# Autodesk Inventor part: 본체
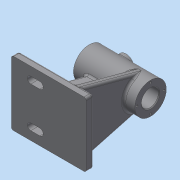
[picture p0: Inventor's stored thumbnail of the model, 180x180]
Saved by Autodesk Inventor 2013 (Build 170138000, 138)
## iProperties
Created: 2019-10
Part Number: 본체
Material: Generic
Document SubType Name: Modeling
Designer: Administrator
Density: 1 g/cm^3
Author: Administrator
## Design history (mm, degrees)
sketch "스케치1"
  geometry: L1 (0, 0)-(127.136, 0); L2 (0, 14.5)-(0, 21); L3 (0, 21)-(82, 21); L4 (82, 21)-(82, 11.5); L5 (82, 11.5)-(62, 11.5); L6 (62, 11.5)-(62, 14.5); L7 (62, 14.5)-(0, 14.5)
  constraints: 14 end point, 3 perpendicular, 2 parallel, 1 horizontal, 1 vertical alignment
  dimensions: "d0" = 42 diameter of L3 L1; "d2" = 29 diameter of L7 L1; "d3" = 23 diameter of L5 L1; "d4" = 62 distance of L6.end L2.start; "d5" = 82 distance between parallel lines of L4 L2
revolve "회전1" sketch "스케치1" stored, may be unused: angle "d6" = 90 deg
sketch "스케치2"
  geometry: C1 r 11.5 at (0, 0) reference; C2 r 2 at (0, 18)
  constraints: 1 centre point, 1 vertical alignment
  dimensions: "d7" = 18 distance of C1.centre C2.centre
hole "구멍1" sketch "스케치2" at (0, 18) diameter "d8" = 2.459; stored, may be unused: countersink angle "d12" = 82 deg, drill point angle "d14" = 118 deg; dims "d9" = 8, "d10" = 3.023, "d11" = 2, "d13" = 10
node "작업 평면1"
chamfer "모따기1" distance "d18" = 1; stored, may be unused: second distance "d19" = 2, angle "d20" = 45 deg
node "작업 평면2"
sketch "스케치3"
  geometry: C1 r 11 at (-25, 0); 1 further point
  constraints: 1 centre point, 1 horizontal alignment
  dimensions: "d22" = 25 distance of point (0, 0) C1.centre; "d23" = 22 diameter of C1
extrude "돌출1" join sketch "스케치3" stored distance "d24" = 10; taper "d25" = 0 deg
sketch "스케치4"
  geometry: C1 r 11 at (0, 0) reference; C2 r 7 at (0, 0); 1 further point
  constraints: 1 centre point, 1 coincident
  dimensions: "d26" = 14 diameter of C2
extrude "돌출2" cut sketch "스케치4" distance "d28" = 4; taper "d29" = 0 deg
sketch "스케치5"
  geometry: C1 r 7 at (0, 0) reference; C2 r 3.162 at (0, 0); 1 further point
  constraints: 1 centre point, 1 coincident
hole "구멍2" sketch "스케치5" at (0, 0) diameter "d30" = 4.917; stored, may be unused: countersink angle "d34" = 82 deg, drill point angle "d36" = 118 deg; dims "d31" = 8, "d32" = 3.023, "d33" = 2, "d35" = 10
fillet "모깎기1" dims "d37" = 3
node "작업 평면3"
sketch "스케치6"
  geometry: L1 (18, -43)-(-82, -43); L2 (-82, -43)-(-82, 43); L3 (-82, 43)-(18, 43); L4 (18, 43)-(18, -43); L5 (-82, 21)-(-82, -21) reference; 1 further point
  constraints: 8 end point, 2 parallel, 1 horizontal, 1 perpendicular
  dimensions: "d39" = 0 distance between parallel lines of L5 L2; "d40" = 100 distance of L1.start L1.end; "d41" = 86 distance of L1.end L2.end; "d42" = 43 distance from line of L1 point (0, 0)
extrude "돌출3" join sketch "스케치6" distance "d43" = 10; taper "d44" = 0 deg
fillet "모깎기2" dims "d45" = 3
sketch "스케치7"
  geometry: L1 (8, 31.5)-(20, 31.5); L2 (8, 22.5)-(20, 22.5); L3 (8, 34)-(20, 34); L4 (8, 20)-(20, 20); L5 (-18, 40)-(-18, -40) reference; A1 r 4.5 centre (8, 27) between (8, 31.5) and (8, 22.5); A2 r 4.5 centre (20, 27) between (20, 22.5) and (20, 31.5); A3 r 7 centre (20, 27) between (20, 20) and (20, 34); A4 r 7 centre (8, 27) between (8, 34) and (8, 20); 1 further point
  constraints: 8 end point, 8 point on circle, 8 tangent, 4 centre point, 2 coincident, 2 equal radius, 1 horizontal alignment
  dimensions: "d46" = 9 diameter of A1; "d49" = 27 vertical distance of A1.centre point (0, 0); "d50" = 12 distance of A2.centre A1.centre; "d51" = 14 diameter of A4; "d52" = 26 distance from line of L5 A1.centre
extrude "돌출4" join sketch "스케치7" distance "d53" = 3; taper "d54" = 0 deg
node "작업 평면4"
fillet "모깎기3" dims "d55" = 3
sketch "스케치8"
  geometry: L1 (20, 31.5)-(8, 31.5) reference; L2 (8, 22.5)-(20, 22.5) reference; L3 (20, -22.5)-(8, -22.5) reference; L4 (8, -31.5)-(20, -31.5) reference; A1 r 4.5 centre (8, 27) between (8, 31.5) and (8, 22.5) reference; A2 r 4.5 centre (20, 27) between (20, 22.5) and (20, 31.5) reference; A3 r 4.5 centre (8, -27) between (8, -22.5) and (8, -31.5) reference; A4 r 4.5 centre (20, -27) between (20, -31.5) and (20, -22.5) reference; 1 further point
extrude "돌출5" cut sketch "스케치8" stored distance "d56" = 3; taper "d57" = 0 deg
node "작업 평면5"
sketch "스케치9"
  geometry: L1 (-76, 40)-(-76, -40) reference; L2 (-79, -43)-(-86, -43) reference; L3 (-86, -43)-(-86, 43) reference; L4 (-86, 43)-(-79, 43) reference; L5 (-78.217, -42.896)-(5.48, -20.272); L6 (-78.217, 42.896)-(5.48, 20.272); L7 (-76, 40)-(-76, -40); C1 r 14.5 at (0, 0) reference; C2 r 11.5 at (0, 0) reference; A1 r 3 centre (-79, -40) between (-79, -43) and (-76, -40) reference; A2 r 3 centre (-79, 40) between (-76, 40) and (-79, 43) reference; A3 r 3 centre (-79, 40) between (-76, 40) and (-79, 43) reference; A4 r 3 centre (-79, -40) between (-79, -43) and (-76, -40) reference; A5 r 21 centre (0, 0) between (5.48, 20.272) and (5.48, -20.272) reference; A6 r 21 centre (0, 0) between (5.48, 20.272) and (5.48, -20.272); A7 r 3 centre (-79, 40) between (-76, 40) and (-78.217, 42.896); A8 r 3 centre (-79, -40) between (-79, -43) and (-76, -40); 2 further points
  constraints: 15 tangent, 10 point on circle, 6 end point, 3 centre point, 1 collinear, 2 other
extrude "돌출6" join sketch "스케치9" stored distance "d59" = 10; taper "d60" = 0 deg
fillet "모깎기4" dims "d61" = 3
node "작업 평면6"
sketch "스케치10"
  geometry: L1 (0, 10)-(69.208, 10) reference; L2 (15, 65)-(97, 65) reference; L3 (12, 10)-(32.018, 65); L4 (-3, 0)-(-3, 7) reference; 1 further point
  constraints: 2 end point, 2 point on line
  dimensions: "d62" = 15 distance from line of L4 L3.start; "d63" = 70 deg angle of L1 L3
feature "리브1" sketch "스케치10" dims "d64" = 1, "d65" = 10, "d66" = 0, "d67" = 0, "d68" = 1, "d69" = 1
fillet "모깎기5" dims "d70" = 3
sketch "스케치11"
  geometry: L1 (-15, -43)-(79, -43) reference; L2 (82, -40)-(82, 40) reference; 2 further points
  constraints: 1 other
  dimensions: "d71" = 43 distance from line of L1 point (75, 0); "d72" = 7 distance from line of L2 point (75, 0)
extrude "돌출7" join sketch "스케치11" distance "d73" = 0.5; taper "d74" = 0 deg
node "솔리드1"
pattern_circular "원형 패턴1" dims angle "d16" = 360 deg
mirror "대칭1"
mirror "대칭2"
node "절단 모서리 투영1"
other parameters: "d21" = 24, "d38" = -86, "d58" = 62
